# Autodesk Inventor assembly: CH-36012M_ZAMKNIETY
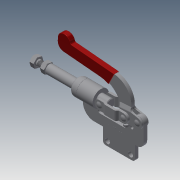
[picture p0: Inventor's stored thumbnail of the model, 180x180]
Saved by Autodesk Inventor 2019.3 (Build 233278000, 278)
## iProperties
Company: Î¢ÈíÖÐ¹ú
Created: 2012-09
Part Number: CH-36012M_ZAMKNIETY
Material: Ogólny
Description: STEP AP203
Document SubType Name: Assembly
Designer: CADENGINEERING4
Sending System: SolidWorks 2010
Preprocessor: SwSTEP 2.0
Title: CH-36012M.STEP
Author: Î¢ÈíÓÃ»§
Revision Number: ÈÎºÎ
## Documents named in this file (13)
- D:\Vault_2016\Projekty\STRONA\Push-pull clamp\CH-36012M\CH-36012M_ZAMKNIETY.iam
- D:\Vault_2016\Projekty\STRONA\Push-pull clamp\CH-36012M\CH-36010M-04 CONNECTING-PLATE.ipt
- D:\Vault_2016\Projekty\STRONA\Push-pull clamp\CH-36012M\CH-36010M-11.ipt
- D:\Vault_2016\Projekty\STRONA\Push-pull clamp\CH-36012M\CH-36010M-08.ipt
- D:\Vault_2016\Projekty\STRONA\Push-pull clamp\CH-36012M\CH-36012M-01 BASE.ipt
- D:\Vault_2016\Projekty\STRONA\Push-pull clamp\CH-36012M\CH-36010M-03 HANDLE.ipt
- D:\Vault_2016\Projekty\STRONA\Push-pull clamp\CH-36012M\CH-36010M-02 CREST STALK.ipt
- D:\Vault_2016\Projekty\STRONA\Push-pull clamp\CH-36012M\CH-36010M-05 LEAD SET.ipt
- D:\Vault_2016\Projekty\STRONA\Push-pull clamp\CH-36012M\CH-SA-105015 SPINDLE SUPPLIED.ipt
- D:\Vault_2016\Projekty\STRONA\Push-pull clamp\CH-36012M\CH-36010M-10.ipt
- D:\Vault_2016\Projekty\STRONA\Push-pull clamp\CH-36012M\M10 Nut.ipt
- D:\Vault_2016\Projekty\STRONA\Push-pull clamp\CH-36012M\CH-36010M-09.ipt
- D:\Vault_2016\Projekty\STRONA\Push-pull clamp\CH-36012M\CH-36010M-07.ipt
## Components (13 placed, 13 different names)
1. CH-36010M-04 CONNECTING-PLATE_1
2. CH-36010M-11_2
3. CH-36010M-08_3
4. CH-36012M-01 BASE_4
5. CH-36010M-03 HANDLE_5
6. CH-36010M-02 CREST STALK_6
7. CH-36010M-05 LEAD SET_7
8. CH-SA-105015 SPINDLE SUPPLIED_8
9. CH-36010M-10_9
10. M10 Nut_10
11. CH-36010M-09_11
12. CH-36010M-07_12
13. CH-36010M-04 CONNECTING-PLATE_13
